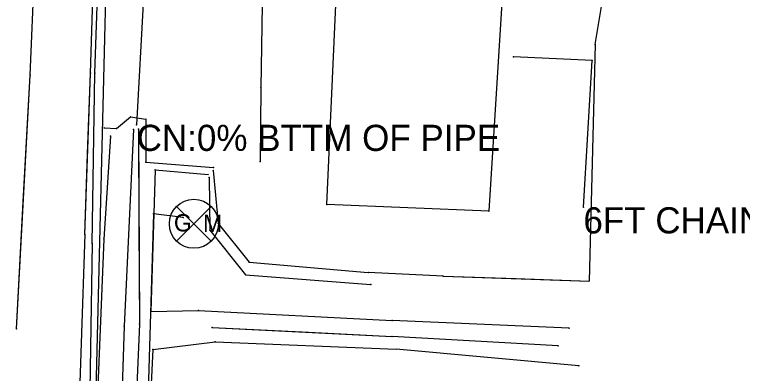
# Model space of a CAD drawing. Extents: x -99999 to 591807, y -99999 to 347168.
# Drawn here: x 591263 to 591402.1, y 321068.6 to 321137.2 of the extents above; entities that cross this region are included whole.
import ezdxf

# ---------------------------------------------------------------- set-up
doc = ezdxf.new("R2010")
doc.units = 0
for name, color, linetype in [('S_BREAKLINE', 7, 'Continuous'), ('S_BUILDING', 7, 'Continuous'), ('S_DITCHLINE', 7, 'Continuous'), ('S_DRG_PT_SYM', 7, 'Continuous'), ('S_EDGE_CONCRETE', 7, 'Continuous'), ('S_EDGE_PAVEMENT', 7, 'Continuous'), ('S_FENCE', 7, 'Continuous'), ('S_FENCE_ANNOT', 7, 'Continuous'), ('S_GAS_UTILITIES', 7, 'Continuous'), ('S_GRD_PT_SYM', 7, 'Continuous'), ('S_MSC_PT_SYM', 7, 'Continuous'), ('S_PAVEMENT_CROWN', 7, 'Continuous'), ('S_RDW_PT_SYM', 7, 'Continuous'), ('S_SHOULDER', 7, 'Continuous'), ('S_SIDE_DRAIN', 7, 'Continuous'), ('S_SIDE_DRAIN_ANNOT', 7, 'Continuous'), ('S_STR_PT_SYM', 7, 'Continuous'), ('S_UTL_PT_SYM', 7, 'Continuous'), ('S_WATER_UTILITIES', 7, 'Continuous')]:
    doc.layers.add(name, color=color, linetype=linetype)

msp = doc.modelspace()

# ---------------------------------------------------------------- linework, layer by layer
at = {"layer": 'S_BREAKLINE'}
for points in [[(591310.72, 321162.69), (591310.13, 321123.24), (591309.99, 321109.12)], [(591371.75, 321100.36), (591373.41, 321128.4), (591358.39, 321129.14)], [(591281.36, 321113.96), (591280.1, 321094.28), (591278.46, 321053.59), (591277.74, 321005.74), (591276.37, 320956.7), (591275.93, 320916.31), (591278.75, 320910.81)], [(591289.89, 321107.53), (591289.11, 321080.44)], [(591289.88, 321107.54), (591300.02, 321106.65)], [(591300.24, 321106.06), (591300.34, 321095.95), (591307.2, 321087.46), (591331.11, 321085.6)], [(591289.11, 321080.44), (591298.18, 321080.61)], [(591298.18, 321080.61), (591335.21, 321078.69)], [(591369.01, 321077.24), (591335.21, 321078.69)], [(591289.48, 321073.18), (591301.39, 321074.63)], [(591301.39, 321074.63), (591335.99, 321073.2)], [(591289.48, 321073.18), (591287.44, 321031.1), (591286.36, 320997.24), (591285.76, 320979.11), (591282.6, 320927.54), (591281.77, 320916.31), (591282.92, 320915.49)], [(591370.87, 321070.06), (591335.99, 321073.2)]]:
    msp.add_lwpolyline(points, dxfattribs=at)
at = {"layer": 'S_BUILDING'}
for p, q in [((591322.7, 321100.88), (591325.87, 321170.79)), ((591358.07, 321169.82), (591353.69, 321099.64)), ((591353.69, 321099.64), (591322.7, 321100.88))]:
    msp.add_line(p, q, dxfattribs=at)
at = {"layer": 'S_DITCHLINE'}
for points in [[(591285.77, 321115.22), (591284.01, 321077.62), (591282.43, 321030.91), (591282.45, 320997.38), (591281.01, 320979.45), (591278.52, 320928.42), (591279.85, 320915.15), (591281.25, 320911.6)], [(591285.77, 321115.22), (591284.89, 321096.42), (591284.01, 321077.62), (591283.22, 321054.26), (591282.43, 321030.91), (591282.44, 321014.14), (591282.45, 320997.38), (591281.01, 320979.45), (591280.39, 320966.69), (591279.77, 320953.94), (591279.15, 320941.18), (591278.52, 320928.42), (591279.85, 320915.15), (591281.25, 320911.6)], [(591286.73, 321115.28), (591286.9, 321078.02), (591284.89, 321031.07), (591283.78, 320997.54), (591282.22, 320979.28), (591280.69, 320927.89), (591280.97, 320915.41), (591282.29, 320911.91)], [(591286.73, 321115.28), (591286.82, 321096.65), (591286.9, 321078.02), (591285.9, 321054.54), (591284.89, 321031.07), (591284.33, 321014.31), (591283.78, 320997.54), (591282.22, 320979.28), (591281.84, 320966.43), (591281.46, 320953.58), (591281.07, 320940.74), (591280.69, 320927.89), (591280.97, 320915.41), (591282.29, 320911.91)], [(591300.79, 321077.38), (591335.18, 321075.67)], [(591300.79, 321077.38), (591317.98, 321076.52), (591335.18, 321075.67)], [(591366.9, 321073.88), (591335.18, 321075.67)], [(591366.9, 321073.88), (591351.04, 321074.78), (591335.18, 321075.67)]]:
    msp.add_lwpolyline(points, dxfattribs=at)
at = {"layer": 'S_DRG_PT_SYM'}
msp.add_lwpolyline([(591286.37, 321116.13), (591286.37, 321116.18), (591286.37, 321116.13), (591286.32, 321116.13), (591286.37, 321116.13), (591286.37, 321116.08), (591286.37, 321116.13), (591286.42, 321116.13)], dxfattribs=at)
at = {"layer": 'S_EDGE_CONCRETE'}
for points in [[(591374, 321131.49), (591379.61, 321165.23)], [(591374, 321131.49), (591376.8, 321148.36), (591379.61, 321165.23)], [(591374, 321131.49), (591372.83, 321086.26)], [(591374, 321131.49), (591373.41, 321108.88), (591372.83, 321086.26)], [(591280.15, 321115.52), (591282.5, 321115.39), (591285.2, 321117.63), (591288.15, 321117.18), (591288.12, 321108.98), (591301.06, 321107.98)], [(591280.15, 321115.52), (591282.5, 321115.39), (591285.2, 321117.63), (591288.15, 321117.18), (591288.12, 321108.98), (591301.06, 321107.98)], [(591301.02, 321107.38), (591301.98, 321097.23), (591307.89, 321089.86), (591330.64, 321087.89)], [(591301.02, 321107.38), (591301.98, 321097.23), (591307.89, 321089.86), (591330.64, 321087.89)], [(591344.92, 321087.17), (591330.64, 321087.89)], [(591344.92, 321087.17), (591330.64, 321087.89)], [(591344.92, 321087.17), (591372.83, 321086.26)], [(591344.92, 321087.17), (591358.88, 321086.71), (591372.83, 321086.26)]]:
    msp.add_lwpolyline(points, dxfattribs=at)
at = {"layer": 'S_EDGE_PAVEMENT'}
for points in [[(591276.47, 321095.14), (591277.53, 321126.02), (591278.71, 321162.76), (591279.79, 321192.63), (591281.13, 321235.17), (591281.77, 321259.21), (591283.07, 321300.34), (591284.27, 321341.23), (591285.36, 321368.86)], [(591276.47, 321095.14), (591277, 321110.58), (591277.53, 321126.02), (591278.12, 321144.39), (591278.71, 321162.76), (591279.25, 321177.69), (591279.79, 321192.63), (591280.46, 321213.9), (591281.13, 321235.17), (591281.77, 321259.21), (591282.42, 321279.78), (591283.07, 321300.34), (591283.67, 321320.79), (591284.27, 321341.23), (591284.81, 321355.05)], [(591276.46, 321095.17), (591275.06, 321053.6), (591273.29, 321005.35), (591272, 320957.38), (591270.85, 320912.71), (591269.63, 320868.12), (591267.97, 320823.16), (591266.37, 320784.97), (591264.57, 320741.35), (591263.05, 320704.52), (591261.34, 320660.72), (591259.64, 320623.87), (591258.44, 320586.06), (591256.82, 320543.02), (591255.33, 320500.73), (591253.74, 320460.21), (591252.24, 320423.96)], [(591276.46, 321095.17), (591275.76, 321074.38), (591275.06, 321053.6), (591274.17, 321029.47), (591273.29, 321005.35), (591272.65, 320981.36), (591272, 320957.38), (591271.43, 320935.04), (591270.85, 320912.71), (591270.24, 320890.41)]]:
    msp.add_lwpolyline(points, dxfattribs=at)
at = {"layer": 'S_FENCE'}
for p, q in [((591373.41, 321128.4), (591358.39, 321129.14)), ((591371.75, 321100.36), (591373.41, 321128.4))]:
    msp.add_line(p, q, dxfattribs=at)
for points in [[(591373.41, 321128.4), (591358.39, 321129.14)], [(591371.75, 321100.36), (591373.41, 321128.4)]]:
    msp.add_lwpolyline(points, dxfattribs=at)
at = {"layer": 'S_GAS_UTILITIES'}
for p, q in [((591294, 321093.89), (591300.62, 321100.51)), ((591294, 321100.51), (591300.62, 321093.89)), ((591289.56, 321099.12), (591287.04, 321010.99)), ((591295.28, 321098.39), (591289.56, 321099.12))]:
    msp.add_line(p, q, dxfattribs=at)
msp.add_circle((591297.31, 321097.2), 4.68, dxfattribs=at)
at = {"layer": 'S_GRD_PT_SYM'}
for points in [[(591358.39, 321129.14), (591358.39, 321129.09), (591358.39, 321129.14), (591358.44, 321129.14), (591358.39, 321129.14), (591358.39, 321129.19), (591358.39, 321129.14), (591358.34, 321129.14)], [(591373.41, 321128.4), (591373.41, 321128.35), (591373.41, 321128.4), (591373.46, 321128.4), (591373.41, 321128.4), (591373.42, 321128.45), (591373.41, 321128.4), (591373.36, 321128.4)], [(591310.13, 321123.24), (591310.18, 321123.24), (591310.13, 321123.24), (591310.13, 321123.29), (591310.13, 321123.24), (591310.08, 321123.24), (591310.13, 321123.24), (591310.13, 321123.19)], [(591285.77, 321115.22), (591285.82, 321115.22), (591285.77, 321115.22), (591285.77, 321115.27), (591285.77, 321115.22), (591285.72, 321115.22), (591285.77, 321115.22), (591285.77, 321115.17)], [(591286.73, 321115.28), (591286.78, 321115.28), (591286.73, 321115.28), (591286.73, 321115.33), (591286.73, 321115.28), (591286.68, 321115.28), (591286.73, 321115.28), (591286.73, 321115.23)], [(591281.36, 321113.96), (591281.41, 321113.96), (591281.36, 321113.96), (591281.37, 321114.01), (591281.36, 321113.96), (591281.32, 321113.97), (591281.36, 321113.96), (591281.36, 321113.91)], [(591309.99, 321109.12), (591310.04, 321109.12), (591309.99, 321109.12), (591310, 321109.17), (591309.99, 321109.12), (591309.94, 321109.12), (591309.99, 321109.12), (591309.99, 321109.07)], [(591289.88, 321107.54), (591289.89, 321107.59), (591289.88, 321107.54), (591289.83, 321107.55), (591289.88, 321107.54), (591289.88, 321107.49), (591289.88, 321107.54), (591289.93, 321107.54)], [(591289.89, 321107.53), (591289.94, 321107.53), (591289.89, 321107.53), (591289.89, 321107.58), (591289.89, 321107.53), (591289.84, 321107.53), (591289.89, 321107.53), (591289.89, 321107.48)], [(591300.02, 321106.65), (591300.02, 321106.7), (591300.02, 321106.65), (591299.97, 321106.66), (591300.02, 321106.65), (591300.01, 321106.6), (591300.02, 321106.65), (591300.07, 321106.65)], [(591300.24, 321106.06), (591300.29, 321106.06), (591300.24, 321106.06), (591300.24, 321106.11), (591300.24, 321106.06), (591300.19, 321106.06), (591300.24, 321106.06), (591300.24, 321106.01)], [(591371.75, 321100.36), (591371.7, 321100.37), (591371.75, 321100.36), (591371.75, 321100.31), (591371.75, 321100.36), (591371.8, 321100.36), (591371.75, 321100.36), (591371.76, 321100.41)], [(591300.34, 321095.95), (591300.38, 321095.99), (591300.34, 321095.95), (591300.31, 321095.99), (591300.34, 321095.95), (591300.3, 321095.92), (591300.34, 321095.95), (591300.37, 321095.92)], [(591280.1, 321094.28), (591280.15, 321094.28), (591280.1, 321094.28), (591280.1, 321094.33), (591280.1, 321094.28), (591280.05, 321094.28), (591280.1, 321094.28), (591280.1, 321094.23)], [(591307.2, 321087.46), (591307.2, 321087.51), (591307.2, 321087.46), (591307.15, 321087.47), (591307.2, 321087.46), (591307.2, 321087.41), (591307.2, 321087.46), (591307.25, 321087.46)], [(591331.11, 321085.6), (591331.11, 321085.65), (591331.11, 321085.6), (591331.06, 321085.6), (591331.11, 321085.6), (591331.1, 321085.55), (591331.11, 321085.6), (591331.16, 321085.6)], [(591289.11, 321080.44), (591289.16, 321080.44), (591289.11, 321080.44), (591289.11, 321080.49), (591289.11, 321080.44), (591289.06, 321080.44), (591289.11, 321080.44), (591289.11, 321080.39)], [(591289.11, 321080.44), (591289.11, 321080.49), (591289.11, 321080.44), (591289.06, 321080.44), (591289.11, 321080.44), (591289.11, 321080.39), (591289.11, 321080.44), (591289.16, 321080.44)], [(591298.18, 321080.61), (591298.18, 321080.66), (591298.18, 321080.61), (591298.13, 321080.62), (591298.18, 321080.61), (591298.17, 321080.56), (591298.18, 321080.61), (591298.23, 321080.61)], [(591298.18, 321080.61), (591298.17, 321080.66), (591298.18, 321080.61), (591298.13, 321080.61), (591298.18, 321080.61), (591298.18, 321080.56), (591298.18, 321080.61), (591298.23, 321080.61)], [(591335.21, 321078.69), (591335.22, 321078.74), (591335.21, 321078.69), (591335.16, 321078.69), (591335.21, 321078.69), (591335.21, 321078.64), (591335.21, 321078.69), (591335.26, 321078.68)], [(591335.21, 321078.69), (591335.21, 321078.64), (591335.21, 321078.69), (591335.26, 321078.68), (591335.21, 321078.69), (591335.22, 321078.74), (591335.21, 321078.69), (591335.16, 321078.69)], [(591284.01, 321077.62), (591284.06, 321077.61), (591284.01, 321077.62), (591284.01, 321077.67), (591284.01, 321077.62), (591283.96, 321077.62), (591284.01, 321077.62), (591284.01, 321077.57)], [(591286.9, 321078.02), (591286.95, 321078.02), (591286.9, 321078.02), (591286.91, 321078.07), (591286.9, 321078.02), (591286.85, 321078.02), (591286.9, 321078.02), (591286.9, 321077.97)], [(591300.79, 321077.38), (591300.79, 321077.43), (591300.79, 321077.38), (591300.74, 321077.38), (591300.79, 321077.38), (591300.78, 321077.33), (591300.79, 321077.38), (591300.84, 321077.38)], [(591369.01, 321077.24), (591369.01, 321077.29), (591369.01, 321077.24), (591368.96, 321077.24), (591369.01, 321077.24), (591369.01, 321077.19), (591369.01, 321077.24), (591369.06, 321077.24)], [(591369.01, 321077.24), (591369, 321077.19), (591369.01, 321077.24), (591369.06, 321077.24), (591369.01, 321077.24), (591369.01, 321077.29), (591369.01, 321077.24), (591368.96, 321077.24)], [(591335.18, 321075.67), (591335.18, 321075.72), (591335.18, 321075.67), (591335.13, 321075.67), (591335.18, 321075.67), (591335.18, 321075.62), (591335.18, 321075.67), (591335.23, 321075.67)], [(591335.18, 321075.67), (591335.18, 321075.62), (591335.18, 321075.67), (591335.23, 321075.67), (591335.18, 321075.67), (591335.18, 321075.72), (591335.18, 321075.67), (591335.13, 321075.67)], [(591301.39, 321074.63), (591301.39, 321074.68), (591301.39, 321074.63), (591301.34, 321074.63), (591301.39, 321074.63), (591301.39, 321074.58), (591301.39, 321074.63), (591301.44, 321074.63)], [(591301.39, 321074.63), (591301.38, 321074.68), (591301.39, 321074.63), (591301.34, 321074.62), (591301.39, 321074.63), (591301.39, 321074.58), (591301.39, 321074.63), (591301.44, 321074.64)], [(591289.48, 321073.18), (591289.53, 321073.17), (591289.48, 321073.18), (591289.48, 321073.23), (591289.48, 321073.18), (591289.43, 321073.18), (591289.48, 321073.18), (591289.48, 321073.13)], [(591289.48, 321073.18), (591289.48, 321073.23), (591289.48, 321073.18), (591289.43, 321073.17), (591289.48, 321073.18), (591289.49, 321073.13), (591289.48, 321073.18), (591289.53, 321073.18)], [(591335.99, 321073.2), (591335.99, 321073.24), (591335.99, 321073.2), (591335.94, 321073.2), (591335.99, 321073.2), (591335.99, 321073.15), (591335.99, 321073.2), (591336.04, 321073.19)], [(591335.99, 321073.2), (591335.98, 321073.15), (591335.99, 321073.2), (591336.04, 321073.19), (591335.99, 321073.2), (591335.99, 321073.24), (591335.99, 321073.2), (591335.94, 321073.2)], [(591366.9, 321073.88), (591366.9, 321073.93), (591366.9, 321073.88), (591366.85, 321073.88), (591366.9, 321073.88), (591366.9, 321073.83), (591366.9, 321073.88), (591366.95, 321073.88)], [(591366.9, 321073.88), (591366.9, 321073.83), (591366.9, 321073.88), (591366.95, 321073.88), (591366.9, 321073.88), (591366.9, 321073.93), (591366.9, 321073.88), (591366.85, 321073.89)], [(591370.87, 321070.06), (591370.87, 321070.11), (591370.87, 321070.06), (591370.82, 321070.06), (591370.87, 321070.06), (591370.87, 321070.01), (591370.87, 321070.06), (591370.92, 321070.06)], [(591370.87, 321070.06), (591370.86, 321070.01), (591370.87, 321070.06), (591370.92, 321070.05), (591370.87, 321070.06), (591370.87, 321070.11), (591370.87, 321070.06), (591370.82, 321070.06)]]:
    msp.add_lwpolyline(points, close=True, dxfattribs=at)
at = {"layer": 'S_MSC_PT_SYM'}
for points in [[(591358.39, 321129.14), (591358.39, 321129.19), (591358.39, 321129.14), (591358.34, 321129.14), (591358.39, 321129.14), (591358.39, 321129.09), (591358.39, 321129.14), (591358.44, 321129.14)], [(591373.41, 321128.4), (591373.41, 321128.45), (591373.41, 321128.4), (591373.36, 321128.4), (591373.41, 321128.4), (591373.41, 321128.35), (591373.41, 321128.4), (591373.46, 321128.4)], [(591371.75, 321100.36), (591371.75, 321100.41), (591371.75, 321100.36), (591371.7, 321100.36), (591371.75, 321100.36), (591371.75, 321100.31), (591371.75, 321100.36), (591371.8, 321100.36)]]:
    msp.add_lwpolyline(points, dxfattribs=at)
at = {"layer": 'S_PAVEMENT_CROWN'}
for points in [[(591263.38, 321077.12), (591265.99, 321125.62), (591267.67, 321164.95), (591268.53, 321193.03), (591270.16, 321236.57), (591270.82, 321259.67), (591272.06, 321300.96), (591273.09, 321336.11), (591274.57, 321369.52)], [(591263.38, 321077.12), (591264.69, 321101.37), (591265.99, 321125.62), (591266.83, 321145.29), (591267.67, 321164.95), (591268.1, 321178.99), (591268.53, 321193.03), (591269.35, 321214.8), (591270.16, 321236.57), (591270.82, 321259.67), (591271.44, 321280.32), (591272.06, 321300.96), (591272.58, 321318.54), (591273.09, 321336.11), (591273.83, 321352.81)]]:
    msp.add_lwpolyline(points, dxfattribs=at)
at = {"layer": 'S_RDW_PT_SYM'}
for points in [[(591374, 321131.49), (591373.95, 321131.5), (591374, 321131.49), (591373.99, 321131.44), (591374, 321131.49), (591374.05, 321131.48), (591374, 321131.49), (591374, 321131.54)], [(591374, 321131.49), (591374.05, 321131.49), (591374, 321131.49), (591374, 321131.54), (591374, 321131.49), (591373.95, 321131.49), (591374, 321131.49), (591374, 321131.44)], [(591265.99, 321125.62), (591265.94, 321125.62), (591265.99, 321125.62), (591265.99, 321125.57), (591265.99, 321125.62), (591266.04, 321125.61), (591265.99, 321125.62), (591266, 321125.67)], [(591277.53, 321126.02), (591277.48, 321126.02), (591277.53, 321126.02), (591277.53, 321125.97), (591277.53, 321126.02), (591277.58, 321126.02), (591277.53, 321126.02), (591277.53, 321126.07)], [(591278.37, 321126.02), (591278.32, 321126.02), (591278.37, 321126.02), (591278.37, 321125.97), (591278.37, 321126.02), (591278.42, 321126.01), (591278.37, 321126.02), (591278.37, 321126.07)], [(591285.2, 321117.63), (591285.21, 321117.68), (591285.2, 321117.63), (591285.15, 321117.64), (591285.2, 321117.63), (591285.19, 321117.58), (591285.2, 321117.63), (591285.25, 321117.62)], [(591288.15, 321117.18), (591288.2, 321117.18), (591288.15, 321117.18), (591288.15, 321117.23), (591288.15, 321117.18), (591288.1, 321117.18), (591288.15, 321117.18), (591288.15, 321117.13)], [(591280.15, 321115.52), (591280.16, 321115.57), (591280.15, 321115.52), (591280.1, 321115.53), (591280.15, 321115.52), (591280.15, 321115.47), (591280.15, 321115.52), (591280.2, 321115.52)], [(591282.5, 321115.39), (591282.47, 321115.43), (591282.5, 321115.39), (591282.46, 321115.36), (591282.5, 321115.39), (591282.53, 321115.35), (591282.5, 321115.39), (591282.54, 321115.42)], [(591288.12, 321108.98), (591288.13, 321109.03), (591288.12, 321108.98), (591288.07, 321108.99), (591288.12, 321108.98), (591288.12, 321108.93), (591288.12, 321108.98), (591288.17, 321108.98)], [(591301.02, 321107.38), (591301.07, 321107.38), (591301.02, 321107.38), (591301.02, 321107.43), (591301.02, 321107.38), (591300.97, 321107.37), (591301.02, 321107.38), (591301.03, 321107.33)], [(591301.06, 321107.98), (591301.07, 321108.03), (591301.06, 321107.98), (591301.01, 321107.99), (591301.06, 321107.98), (591301.06, 321107.93), (591301.06, 321107.98), (591301.11, 321107.98)], [(591301.98, 321097.23), (591302.02, 321097.26), (591301.98, 321097.23), (591301.95, 321097.27), (591301.98, 321097.23), (591301.94, 321097.2), (591301.98, 321097.23), (591302.01, 321097.19)], [(591276.46, 321095.17), (591276.51, 321095.17), (591276.46, 321095.17), (591276.47, 321095.22), (591276.46, 321095.17), (591276.41, 321095.17), (591276.46, 321095.17), (591276.46, 321095.12)], [(591276.47, 321095.14), (591276.42, 321095.14), (591276.47, 321095.14), (591276.47, 321095.09), (591276.47, 321095.14), (591276.52, 321095.14), (591276.47, 321095.14), (591276.48, 321095.19)], [(591277.87, 321093.47), (591277.92, 321093.47), (591277.87, 321093.47), (591277.87, 321093.52), (591277.87, 321093.47), (591277.82, 321093.47), (591277.87, 321093.47), (591277.87, 321093.42)], [(591277.89, 321093.4), (591277.84, 321093.4), (591277.89, 321093.4), (591277.89, 321093.35), (591277.89, 321093.4), (591277.94, 321093.4), (591277.89, 321093.4), (591277.89, 321093.45)], [(591307.89, 321089.86), (591307.89, 321089.91), (591307.89, 321089.86), (591307.84, 321089.87), (591307.89, 321089.86), (591307.88, 321089.81), (591307.89, 321089.86), (591307.94, 321089.86)], [(591330.64, 321087.89), (591330.65, 321087.93), (591330.64, 321087.89), (591330.59, 321087.89), (591330.64, 321087.89), (591330.64, 321087.84), (591330.64, 321087.89), (591330.69, 321087.88)], [(591330.64, 321087.89), (591330.64, 321087.84), (591330.64, 321087.89), (591330.69, 321087.88), (591330.64, 321087.89), (591330.65, 321087.93), (591330.64, 321087.89), (591330.59, 321087.89)], [(591344.92, 321087.17), (591344.93, 321087.22), (591344.92, 321087.17), (591344.87, 321087.17), (591344.92, 321087.17), (591344.92, 321087.12), (591344.92, 321087.17), (591344.97, 321087.17)], [(591344.92, 321087.17), (591344.92, 321087.12), (591344.92, 321087.17), (591344.97, 321087.16), (591344.92, 321087.17), (591344.93, 321087.22), (591344.92, 321087.17), (591344.87, 321087.17)], [(591372.83, 321086.26), (591372.83, 321086.31), (591372.83, 321086.26), (591372.78, 321086.26), (591372.83, 321086.26), (591372.83, 321086.21), (591372.83, 321086.26), (591372.88, 321086.26)], [(591372.83, 321086.26), (591372.88, 321086.26), (591372.83, 321086.26), (591372.83, 321086.31), (591372.83, 321086.26), (591372.78, 321086.26), (591372.83, 321086.26), (591372.83, 321086.21)], [(591263.38, 321077.12), (591263.33, 321077.13), (591263.38, 321077.12), (591263.38, 321077.07), (591263.38, 321077.12), (591263.43, 321077.12), (591263.38, 321077.12), (591263.39, 321077.17)]]:
    msp.add_lwpolyline(points, close=True, dxfattribs=at)
at = {"layer": 'S_SHOULDER'}
for points in [[(591277.89, 321093.4), (591278.37, 321126.02), (591279.65, 321162.65), (591281.16, 321192.69), (591282.89, 321235.06), (591283.26, 321259.04), (591285.07, 321300.2), (591286.25, 321341.03), (591286.96, 321368.53)], [(591277.89, 321093.4), (591278.13, 321109.71), (591278.37, 321126.02), (591279.01, 321144.33), (591279.65, 321162.65), (591280.41, 321177.67), (591281.16, 321192.69), (591282.02, 321213.87), (591282.89, 321235.06), (591283.26, 321259.04), (591284.17, 321279.62), (591285.07, 321300.2), (591285.66, 321320.62), (591286.25, 321341.03), (591286.61, 321354.78)], [(591277.87, 321093.47), (591277.22, 321053.48), (591276.53, 321005.54), (591275.05, 320957.05), (591274.32, 320914.85)], [(591277.87, 321093.47), (591277.55, 321073.47), (591277.22, 321053.48), (591276.88, 321029.51), (591276.53, 321005.54), (591275.79, 320981.3), (591275.05, 320957.05), (591274.68, 320935.95), (591274.32, 320914.85)]]:
    msp.add_lwpolyline(points, dxfattribs=at)
at = {"layer": 'S_SIDE_DRAIN'}
msp.add_line((591288.99, 321164.97), (591286.37, 321116.13), dxfattribs=at)
at = {"layer": 'S_STR_PT_SYM'}
for points in [[(591322.7, 321100.88), (591322.7, 321100.93), (591322.7, 321100.88), (591322.65, 321100.88), (591322.7, 321100.88), (591322.7, 321100.83), (591322.7, 321100.88), (591322.75, 321100.88)], [(591353.69, 321099.64), (591353.69, 321099.69), (591353.69, 321099.64), (591353.64, 321099.64), (591353.69, 321099.64), (591353.69, 321099.59), (591353.69, 321099.64), (591353.74, 321099.64)]]:
    msp.add_lwpolyline(points, dxfattribs=at)
at = {"layer": 'S_UTL_PT_SYM'}
for points in [[(591289.56, 321099.12), (591289.56, 321099.17), (591289.56, 321099.12), (591289.51, 321099.12), (591289.56, 321099.12), (591289.56, 321099.07), (591289.56, 321099.12), (591289.61, 321099.12)], [(591295.28, 321098.39), (591295.28, 321098.44), (591295.28, 321098.39), (591295.23, 321098.39), (591295.28, 321098.39), (591295.28, 321098.34), (591295.28, 321098.39), (591295.33, 321098.39)]]:
    msp.add_lwpolyline(points, dxfattribs=at)
at = {"layer": 'S_WATER_UTILITIES'}
msp.add_line((591282.12, 321206.66), (591277.24, 321013.57), dxfattribs=at)

# ---------------------------------------------------------------- texts
at = {"layer": 'S_FENCE_ANNOT'}
msp.add_text('6FT CHAIN LNK 3 BARB CN:GOOD', height=5, dxfattribs=at).set_placement((591371.75, 321095.36))
at = {"layer": 'S_GAS_UTILITIES'}
for s, p in [('G', (591293.49, 321095.74)), ('M', (591299.05, 321095.63))]:
    msp.add_text(s, height=3.3, rotation=360, dxfattribs=at).set_placement(p)
at = {"layer": 'S_SIDE_DRAIN_ANNOT'}
msp.add_text('CN:0% BTTM OF PIPE', height=5, dxfattribs=at).set_placement((591286.37, 321111.13))

doc.saveas('drawing.dxf')
